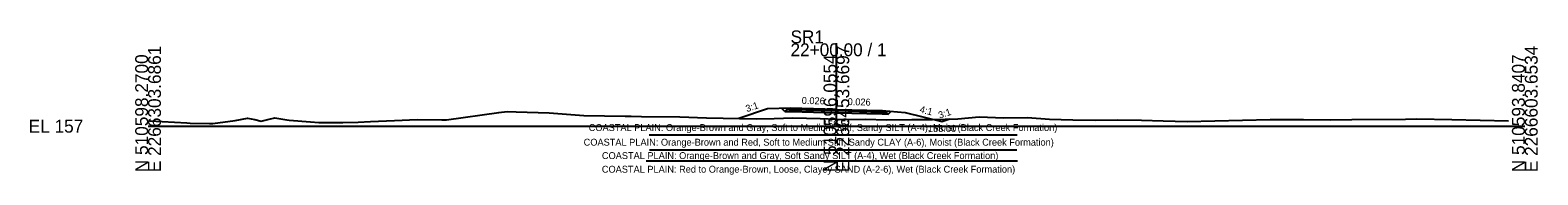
# Model space of a CAD drawing. Extents: x -1079 to 303, y -11 to 4017.
# Drawn here: x -25.7 to 302.8, y 989.5 to 1020.8 of the extents above; entities that cross this region are included whole.
import ezdxf

# ---------------------------------------------------------------- set-up
doc = ezdxf.new("R2010")
doc.units = 0
for name, color, linetype in [('Default', 7, 'Continuous'), ('Exist Cross Section Cell', 7, 'Continuous'), ('Exist XS Center Line Elevation Label', 7, 'Continuous'), ('Exist XS Ground Line', 7, 'Continuous'), ('Prop CMT Pvmt Course 1', 7, 'Continuous'), ('Prop CMT Pvmt Course 2', 7, 'Continuous'), ('Prop CMT Pvmt Course 3', 7, 'Continuous'), ('Prop CMT Pvmt Surface', 7, 'Continuous'), ('Prop CMT Pvmt Surface Shoulder', 7, 'Continuous'), ('Prop CMT Shld Paved Course 1', 7, 'Continuous'), ('Prop CMT Shld Paved Course 2', 7, 'Continuous'), ('Prop CMT Shld Paved Course 3', 7, 'Continuous'), ('Prop CMT Slope Grass', 7, 'Continuous'), ('Prop CMT Subgrade Earthwork', 7, 'Continuous'), ('Prop Road Sect_ Material - Contact (General - Minor)', 7, 'Continuous'), ('Prop Road Sect_ Material - Tx (Composite Desc)', 7, 'Continuous'), ('Prop XS Ditch Standard Text', 7, 'Continuous'), ('Prop XS SE Text', 7, 'Continuous'), ('Prop XS Side Slope Text', 7, 'Continuous')]:
    doc.layers.add(name, color=color, linetype=linetype)

msp = doc.modelspace()

# ---------------------------------------------------------------- linework, layer by layer
at = {"layer": 'Exist Cross Section Cell'}
for p, q in [((150, 1000), (150, 1018)), ((0, 1000), (150, 1000)), ((150, 1000), (300, 1000))]:
    msp.add_line(p, q, dxfattribs=at)
at = {"layer": 'Exist XS Ground Line'}
msp.add_lwpolyline([(0, 1001.24), (0.37, 1001.19), (8.42, 1000.75), (9.19, 1000.69), (13.39, 1000.62), (14.09, 1000.61), (18.99, 1001.2), (21.65, 1001.75), (23.24, 1001.42), (24.68, 1001.1), (26.37, 1001.51), (27.65, 1001.79), (28.9, 1001.59), (30.23, 1001.38), (30.74, 1001.3), (35.37, 1000.94), (37.22, 1000.81), (42.45, 1000.82), (45.78, 1000.86), (48.5, 1001.01), (53.7, 1001.25), (58.62, 1001.47), (64.04, 1001.41), (65.02, 1001.39), (76.46, 1002.97), (78.27, 1003.17), (80.24, 1003.11), (87.43, 1002.92), (94.95, 1002.34), (103.97, 1002.18), (105.29, 1002.15), (107.49, 1002.12), (115.84, 1002), (121.71, 1001.81), (132.48, 1001.57), (136.43, 1001.66), (140.51, 1001.79), (146.44, 1001.66), (150, 1001.51), (150.66, 1001.48), (156.44, 1001.5), (160.81, 1001.36), (166.44, 1001.44), (170.96, 1001.45), (176.44, 1001.62), (181.12, 1002), (186.45, 1001.81), (191.62, 1001.9), (196.45, 1001.53), (201.48, 1001.41), (206.45, 1001.34), (211.33, 1001.35), (216.45, 1001.28), (221.19, 1001.16), (226.46, 1001.05), (244.49, 1001.43), (245.61, 1001.45), (251.8, 1001.42), (257.73, 1001.4), (262.28, 1001.44), (273.99, 1001.56), (276.47, 1001.63), (284.09, 1001.46), (296.47, 1001.15)], dxfattribs=at)
at = {"layer": 'Prop CMT Pvmt Course 1'}
for points in [[(150, 1003.66), (140, 1003.91)], [(140, 1003.91), (140, 1003.66)], [(140, 1003.66), (150, 1003.41)], [(150, 1003.41), (150, 1003.66)], [(150, 1003.66), (160, 1003.4)], [(150, 1003.41), (150, 1003.66)], [(160, 1003.15), (150, 1003.41)], [(160, 1003.4), (160, 1003.15)]]:
    msp.add_lwpolyline(points, dxfattribs=at)
msp.add_lwpolyline([(150, 1003.41), (150, 1003.53), (150, 1003.53), (150, 1003.41)], close=True, dxfattribs=at)
msp.add_lwpolyline([(150, 1003.41), (150, 1003.53), (150, 1003.53), (150, 1003.41)], close=True, dxfattribs=at)
at = {"layer": 'Prop CMT Pvmt Course 2'}
for points in [[(140, 1003.66), (150, 1003.41)], [(150, 1003.41), (140, 1003.66)], [(140, 1003.66), (140, 1003.66)], [(150, 1003.41), (150, 1003.41)], [(160, 1003.15), (150, 1003.41)], [(150, 1003.41), (150, 1003.41)], [(150, 1003.41), (160, 1003.15)], [(160, 1003.15), (160, 1003.15)]]:
    msp.add_lwpolyline(points, dxfattribs=at)
at = {"layer": 'Prop CMT Pvmt Course 3'}
for points in [[(150, 1003.41), (140, 1003.66)], [(140, 1003.66), (140, 1003.16)], [(140, 1003.16), (150, 1002.91)], [(150, 1002.91), (150, 1003.41)], [(150, 1003.41), (160, 1003.15)], [(150, 1002.91), (150, 1003.41)], [(160, 1002.65), (150, 1002.91)], [(160, 1003.15), (160, 1002.65)]]:
    msp.add_lwpolyline(points, dxfattribs=at)
at = {"layer": 'Prop CMT Pvmt Surface'}
for q in [(140, 1003.91), (160, 1003.4)]:
    msp.add_line((150, 1003.66), q, dxfattribs=at)
at = {"layer": 'Prop CMT Pvmt Surface Shoulder'}
for p, q in [((140, 1003.91), (140, 1003.91)), ((160, 1003.4), (160, 1003.4))]:
    msp.add_line(p, q, dxfattribs=at)
at = {"layer": 'Prop CMT Shld Paved Course 1'}
for points in [[(140, 1003.91), (140, 1003.91), (139.76, 1003.67)], [(139.76, 1003.67), (140, 1003.66)], [(140, 1003.66), (140, 1003.91)], [(160, 1003.4), (160, 1003.4), (160.26, 1003.14)], [(160, 1003.15), (160, 1003.4)], [(160.26, 1003.14), (160, 1003.15)]]:
    msp.add_lwpolyline(points, dxfattribs=at)
at = {"layer": 'Prop CMT Shld Paved Course 2'}
for points in [[(140, 1003.66), (139.76, 1003.67)], [(139.76, 1003.67), (139.76, 1003.67)], [(139.76, 1003.67), (140, 1003.66)], [(140, 1003.66), (140, 1003.66)], [(160, 1003.15), (160.26, 1003.14)], [(160.26, 1003.14), (160, 1003.15)], [(160, 1003.15), (160, 1003.15)], [(160.26, 1003.14), (160.26, 1003.14)]]:
    msp.add_lwpolyline(points, dxfattribs=at)
at = {"layer": 'Prop CMT Shld Paved Course 3'}
for points in [[(140, 1003.66), (139.76, 1003.67), (139.26, 1003.68), (138.77, 1003.19)], [(138.77, 1003.19), (140, 1003.16)], [(140, 1003.16), (140, 1003.66)], [(160, 1003.15), (160.26, 1003.14), (160.76, 1003.13), (161.27, 1002.62)], [(160, 1002.65), (160, 1003.15)], [(161.27, 1002.62), (160, 1002.65)]]:
    msp.add_lwpolyline(points, dxfattribs=at)
at = {"layer": 'Prop CMT Slope Grass'}
for p, q in [((135, 1003.74), (128.73, 1001.65)), ((140, 1003.91), (135, 1003.74)), ((160, 1003.4), (165, 1003)), ((165, 1003), (173, 1001)), ((173, 1001), (174.71, 1001.57))]:
    msp.add_line(p, q, dxfattribs=at)
at = {"layer": 'Prop CMT Subgrade Earthwork'}
for points in [[(138.77, 1003.19), (138.11, 1003.85)], [(140, 1003.16), (138.77, 1003.19)], [(150, 1002.91), (140, 1003.16)], [(150, 1002.91), (160, 1002.65)], [(160, 1002.65), (161.27, 1002.62)], [(161.27, 1002.62), (161.9, 1003.25)]]:
    msp.add_lwpolyline(points, dxfattribs=at)
at = {"layer": 'Prop Road Sect_ Material - Contact (General - Minor)'}
for p, q in [((109.21, 998.1), (189.38, 998.1)), ((108.57, 992.5), (189.47, 992.5)), ((109.3, 994.85), (189.29, 994.85))]:
    msp.add_line(p, q, dxfattribs=at)

# ---------------------------------------------------------------- texts
at = {"layer": 'Default'}
msp.add_text('-', height=0.0001, dxfattribs=at).set_placement((0, 1000))
at = {"layer": 'Exist Cross Section Cell'}
for s, p in [('SR1', (140, 1018)), ('22+00.00 / 1', (140, 1015.2)), ('EL 157', (-26, 998.6))]:
    msp.add_text(s, height=2.8, dxfattribs=at).set_placement(p)
for s, p in [('N 510598.2700', (0, 990)), ('E 2266303.6861', (2.8, 990)), ('N 510596.0554', (150, 990)), ('E 2266453.6697', (152.8, 990)), ('N 510593.8407', (300, 990)), ('E 2266603.6534', (302.8, 990))]:
    msp.add_text(s, height=2.8, rotation=90, dxfattribs=at).set_placement(p)
at = {"layer": 'Exist XS Center Line Elevation Label'}
msp.add_text('158.51', height=1.5, dxfattribs=at).set_placement((147.06, 999.74))
at = {"layer": 'Prop Road Sect_ Material - Tx (Composite Desc)'}
for s, p in [('COASTAL PLAIN: Orange-Brown and Gray, Soft to Medium Stiff, Sandy SILT (A-4), Moist (Black Creek Formation)', (96.02, 998.95)), ('COASTAL PLAIN: Orange-Brown and Red, Soft to Medium Stiff, Sandy CLAY (A-6), Moist (Black Creek Formation)', (94.92, 995.77)), ('COASTAL PLAIN: Orange-Brown and Gray, Soft Sandy SILT (A-4), Wet (Black Creek Formation)', (98.89, 992.86)), ('COASTAL PLAIN: Red to Orange-Brown, Loose, Clayey SAND (A-2-6), Wet (Black Creek Formation)', (98.88, 989.9))]:
    msp.add_text(s, height=1.5, dxfattribs=at).set_placement(p)
at = {"layer": 'Prop XS Ditch Standard Text'}
msp.add_text('158.00', height=1.5, dxfattribs=at).set_placement((169.96, 998.75))
at = {"layer": 'Prop XS SE Text'}
for p in [(142.42, 1004.85), (152.42, 1004.59)]:
    msp.add_text('0.026', height=1.5, rotation=358.527, dxfattribs=at).set_placement(p)
at = {"layer": 'Prop XS Side Slope Text'}
for s, rotation, p in [('3:1', 18.4332, (130.5, 1003.03)), ('4:1', 345.9638, (168.03, 1003.01)), ('3:1', 18.4332, (172.49, 1001.62))]:
    msp.add_text(s, height=1.5, rotation=rotation, dxfattribs=at).set_placement(p)

doc.saveas('drawing.dxf')
